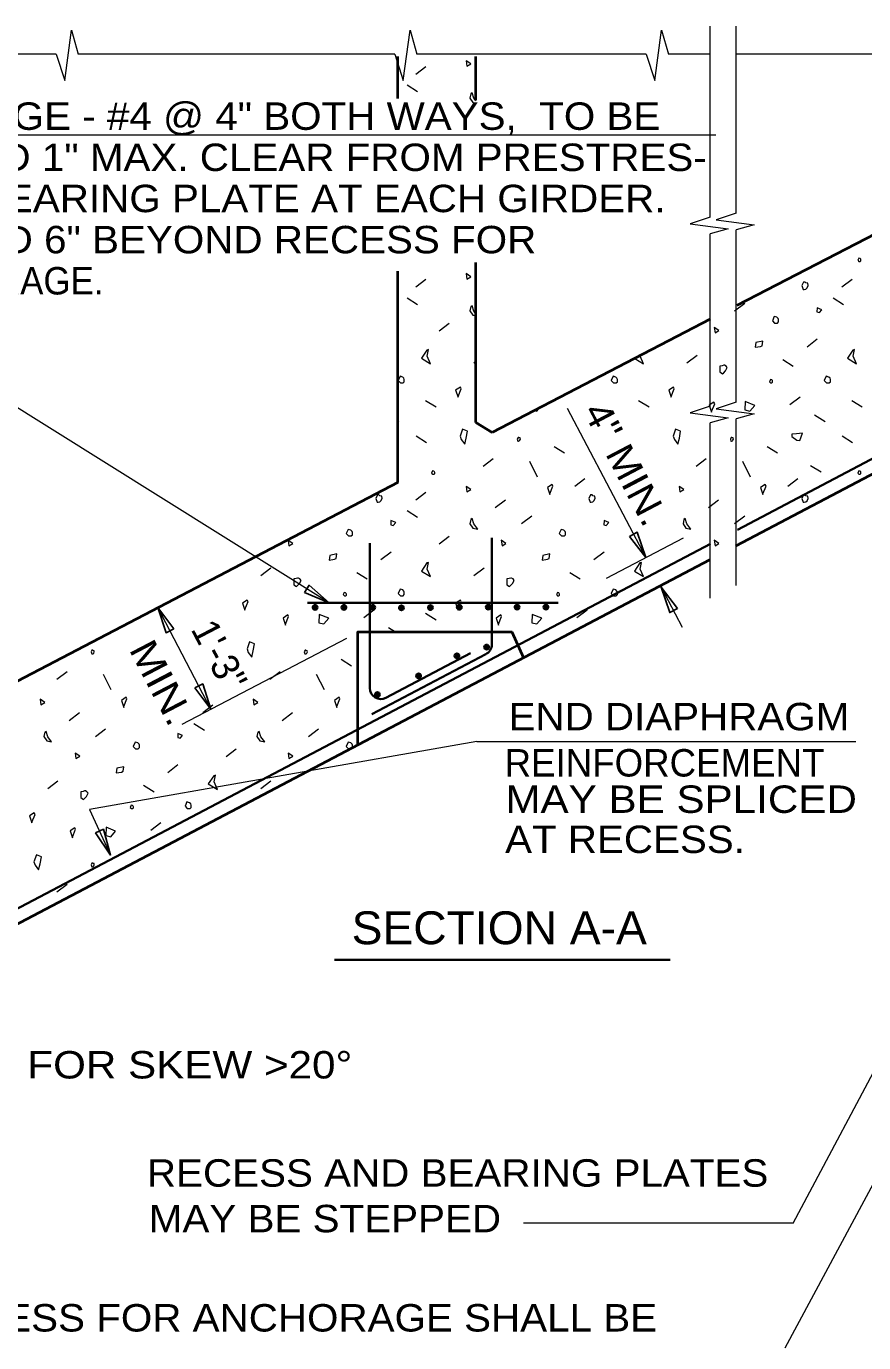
# Model space of a CAD drawing. Extents: x 0 to 22.7, y 0 to 15.6.
# Drawn here: x 3.45 to 6.629, y 5.449 to 10.447 of the extents above; entities that cross this region are included whole.
import ezdxf
from ezdxf.enums import TextEntityAlignment as Align

# ---------------------------------------------------------------- set-up
doc = ezdxf.new("R2010")
doc.units = 0
doc.header["$LTSCALE"] = 0.042
for name, color, linetype, lineweight in [('1', 7, 'Continuous', 13), ('3', 7, 'Continuous', 35), ('4', 7, 'Continuous', 13), ('7', 7, 'Continuous', 13)]:
    doc.layers.add(name, color=color, linetype=linetype, lineweight=lineweight)

msp = doc.modelspace()

# ---------------------------------------------------------------- linework, layer by layer
at = {"layer": '1'}
for p, q in [((6.04656, 10.19172), (6.04656, 10.44672)), ((6.14552, 10.19172), (6.14552, 10.44672)), ((3.56391, 10.3412), (2.69255, 10.3412)), ((4.2125, 10.3412), (3.6476, 10.3412)), ((4.84896, 10.3412), (4.2125, 10.3412)), ((5.80401, 10.3412), (4.93266, 10.3412)), ((6.04667, 10.3412), (5.88771, 10.3412)), ((6.04656, 9.72167), (6.04656, 10.33198)), ((6.60214, 10.3412), (6.14552, 10.3412)), ((6.14552, 9.73688), (6.14552, 10.33198)), ((7.23859, 10.3412), (6.60214, 10.3412)), ((6.04656, 9.00422), (6.04656, 9.6587)), ((6.14552, 9.01943), (6.14552, 9.67391)), ((6.14552, 8.32375), (6.14552, 8.9563)), ((6.04656, 8.27625), (6.04656, 8.94109))]:
    msp.add_line(p, q, dxfattribs=at)
at = {"layer": '1', "lineweight": 40}
for p, q in [((4.86115, 10.17276), (4.86115, 10.33198)), ((5.15703, 10.16615), (5.15703, 10.33198)), ((7.06307, 9.8613), (6.14734, 9.38661)), ((5.15703, 8.94219), (5.15703, 9.54979)), ((4.86115, 8.7151), (4.86115, 9.51661)), ((6.04703, 9.33464), (5.21896, 8.90536)), ((6.14396, 8.47438), (7.51385, 9.19516)), ((5.21896, 8.90536), (5.15703, 8.94219)), ((4.86115, 8.7151), (3.35927, 7.92995)), ((2.61615, 6.61818), (6.04656, 8.42313))]:
    msp.add_line(p, q, dxfattribs=at)
at = {"layer": '1'}
for points in [[(3.56391, 10.3412), (3.59641, 10.24068), (3.62188, 10.43167), (3.6476, 10.3412)], [(4.84896, 10.3412), (4.88151, 10.24057), (4.90698, 10.43167), (4.93266, 10.3412)], [(5.80401, 10.3412), (5.83651, 10.24068), (5.86198, 10.43167), (5.88771, 10.3412)], [(6.04656, 9.72167), (5.97078, 9.69714), (6.11443, 9.67802), (6.04656, 9.6587)], [(6.14552, 9.73688), (6.06974, 9.71234), (6.21339, 9.69323), (6.14552, 9.67391)], [(6.04656, 9.00422), (5.97078, 8.97948), (6.11443, 8.96052), (6.04656, 8.94109)], [(6.14552, 9.01943), (6.06974, 8.99469), (6.21339, 8.97573), (6.14552, 8.9563)]]:
    msp.add_lwpolyline(points, dxfattribs=at)
at = {"layer": '1', "lineweight": 40}
msp.add_lwpolyline([(4.70885, 7.71948), (4.70885, 8.14755), (5.29339, 8.14755), (5.33844, 8.04974)], dxfattribs=at)
at = {"layer": '3'}
for p, q in [((6.14974, 8.53552), (7.49031, 9.24089)), ((5.21776, 8.10036), (5.21776, 8.5049)), ((2.59677, 6.66609), (6.04719, 8.48156)), ((4.75453, 8.48479), (4.75453, 7.93464)), ((4.51828, 8.25786), (5.46922, 8.25786)), ((4.7624, 7.83563), (5.19547, 8.06349)), ((4.81563, 7.89776), (5.13677, 8.06672))]:
    msp.add_line(p, q, dxfattribs=at)
for centre, radius in [((4.54691, 8.24077), 0.0089), ((4.54691, 8.24077), 0.00593), ((4.65629, 8.24077), 0.0089), ((4.65629, 8.24077), 0.00593), ((4.76566, 8.24077), 0.0089), ((4.76566, 8.24077), 0.00593), ((4.87426, 8.2391), 0.0089), ((4.98426, 8.24009), 0.0089), ((4.98426, 8.24009), 0.00593), ((5.09426, 8.24108), 0.0089), ((5.09426, 8.24108), 0.00593), ((5.20426, 8.24212), 0.0089), ((5.20426, 8.24212), 0.00593), ((5.31363, 8.24212), 0.0089), ((5.31363, 8.24212), 0.00593), ((5.42301, 8.24212), 0.0089), ((5.42301, 8.24212), 0.00593), ((4.54691, 8.24077), 0.00297), ((4.65629, 8.24077), 0.00297), ((4.76566, 8.24077), 0.00297), ((4.87426, 8.2391), 0.00593), ((4.87426, 8.2391), 0.00297), ((4.98426, 8.24009), 0.00297), ((5.09426, 8.24108), 0.00297), ((5.20426, 8.24212), 0.00297), ((5.31363, 8.24212), 0.00297), ((5.42301, 8.24212), 0.00297), ((5.1977, 8.0903), 0.0089), ((5.1977, 8.0903), 0.00593), ((5.08535, 8.05686), 0.0089), ((5.08535, 8.05686), 0.00593), ((5.08535, 8.05686), 0.00297), ((5.1977, 8.0903), 0.00297), ((4.93962, 7.98072), 0.0089), ((4.93962, 7.98072), 0.00593), ((4.93962, 7.98072), 0.00297), ((4.78316, 7.90978), 0.0089), ((4.78316, 7.90978), 0.00593), ((4.78316, 7.90978), 0.00297)]:
    msp.add_circle(centre, radius, dxfattribs=at)
for centre, start, end in [((5.17609, 8.10037), 297.75042, 0), ((4.7962, 7.93463), 180, 297.75192)]:
    msp.add_arc(centre, 0.04167, start, end, dxfattribs=at)
at = {"layer": '4'}
for p, q in [((4.59969, 8.25786), (2.78911, 9.39073)), ((5.50302, 8.9974), (5.80167, 8.42979)), ((5.94391, 8.5038), (5.65109, 8.35068)), ((5.86094, 8.31708), (5.94031, 8.1663)), ((4.15151, 7.85401), (3.94932, 8.24078)), ((4.66563, 8.12281), (4.04078, 7.79615)), ((5.16109, 7.7313), (6.59948, 7.7313)), ((6.36161, 5.9025), (7.21276, 7.50573)), ((6.33057, 5.43), (7.13583, 6.92714)), ((6.36161, 5.9025), (5.33776, 5.9025))]:
    msp.add_line(p, q, dxfattribs=at)
at = {"layer": '4', "lineweight": 35}
msp.add_line((4.62057, 6.90219), (5.89427, 6.90219), dxfattribs=at)
at = {"layer": '4'}
for points in [[(6.0675, 10.03359), (2.78911, 10.03359), (2.78911, 9.39073)], [(5.16109, 7.7313), (3.69052, 7.47297), (3.7699, 7.30057)]]:
    msp.add_lwpolyline(points, dxfattribs=at)
at = {"layer": '4', "lineweight": 25}
for points in [[(5.74036, 8.51052), (5.76984, 8.52604), (5.80167, 8.42979)], [(4.50609, 8.29677), (4.52375, 8.32505), (4.59969, 8.25786)], [(5.92224, 8.23635), (5.89276, 8.22083), (5.86094, 8.31708)], [(4.01042, 8.1599), (3.98089, 8.14443), (3.94932, 8.24078)], [(4.09042, 7.9349), (4.11995, 7.95036), (4.15151, 7.85401)], [(3.71292, 7.38443), (3.74323, 7.39839), (3.7699, 7.30057)]]:
    msp.add_lwpolyline(points, close=True, dxfattribs=at)
at = {"layer": '7'}
for p, q in [((4.96771, 10.29339), (4.92917, 10.26406)), ((4.89573, 10.22411), (4.93531, 10.19911)), ((4.96771, 9.48542), (4.92917, 9.45615)), ((6.58526, 9.48542), (6.54677, 9.45615)), ((4.89573, 9.41615), (4.93531, 9.39115)), ((6.51333, 9.41615), (6.55292, 9.39115)), ((6.1776, 9.39464), (6.13911, 9.36531)), ((5.05594, 9.31818), (5.01745, 9.28885)), ((6.4526, 9.25844), (6.41411, 9.22911)), ((5.99677, 9.19724), (5.95828, 9.16792)), ((5.15703, 9.17365), (5.14948, 9.16792)), ((6.32219, 9.18151), (6.36182, 9.15656)), ((4.9662, 9.02667), (5.00573, 9.00182)), ((5.775, 9.02667), (5.81453, 9.00182)), ((6.38776, 9.03859), (6.34927, 9.00932)), ((6.58375, 9.02667), (6.62333, 9.00182)), ((4.86115, 8.94937), (4.8649, 8.94703)), ((6.44286, 8.97203), (6.4825, 8.94703)), ((4.93026, 8.89146), (4.96979, 8.86641)), ((5.45396, 8.85219), (5.49354, 8.82719)), ((6.26276, 8.85219), (6.30234, 8.82719)), ((6.54781, 8.89146), (6.5874, 8.86641)), ((5.22271, 8.80448), (5.18422, 8.77516)), ((5.36, 8.79557), (5.38932, 8.73677)), ((6.03151, 8.80448), (5.99302, 8.77516)), ((6.1688, 8.79557), (6.19813, 8.73677)), ((6.42786, 8.77995), (6.46745, 8.75495)), ((5.57073, 8.72943), (5.53219, 8.70016)), ((6.37948, 8.72943), (6.34099, 8.70016)), ((4.96771, 8.67745), (4.92917, 8.64818)), ((5.26938, 8.64792), (5.23089, 8.61865)), ((6.07818, 8.64792), (6.03969, 8.61865)), ((4.89573, 8.60823), (4.93531, 8.58323)), ((5.36885, 8.58667), (5.33031, 8.5574)), ((6.1776, 8.58667), (6.13911, 8.5574)), ((5.05594, 8.51021), (5.01745, 8.48094)), ((4.835, 8.45047), (4.79651, 8.42115)), ((5.6438, 8.45047), (5.60531, 8.42115)), ((4.37917, 8.38927), (4.34068, 8.36)), ((4.70458, 8.37354), (4.74422, 8.34859)), ((5.18797, 8.38927), (5.14948, 8.36)), ((5.51339, 8.37354), (5.55302, 8.34859)), ((4.77016, 8.23062), (4.73167, 8.20135)), ((4.9662, 8.2187), (5.00573, 8.19385)), ((5.57896, 8.23062), (5.54047, 8.20135)), ((4.82531, 8.16406), (4.85146, 8.14755)), ((3.60516, 7.99651), (3.56667, 7.96719)), ((4.41396, 7.99651), (4.37542, 7.96719)), ((4.64521, 8.04422), (4.68479, 8.01922)), ((3.7424, 7.9876), (3.77177, 7.9288)), ((4.5512, 7.9876), (4.58052, 7.9288)), ((4.15891, 7.86948), (4.12042, 7.84021)), ((3.65182, 7.83995), (3.61333, 7.81068)), ((4.08698, 7.80026), (4.12656, 7.77526)), ((4.46063, 7.83995), (4.42208, 7.81068)), ((3.75125, 7.7787), (3.71276, 7.74943)), ((4.56005, 7.7787), (4.52156, 7.74943)), ((4.24719, 7.70224), (4.20865, 7.67297)), ((4.02625, 7.6425), (3.98771, 7.61323)), ((3.57042, 7.5813), (3.53188, 7.55203)), ((3.89583, 7.56563), (3.93542, 7.54063)), ((4.37917, 7.5813), (4.34068, 7.55203)), ((3.96135, 7.42271), (3.92286, 7.39339)), ((3.60516, 7.18854), (3.56667, 7.15927))]:
    msp.add_line(p, q, dxfattribs=at)
for points in [[(5.12, 10.31599), (5.12292, 10.29531), (5.13771, 10.30422)], [(6.61042, 9.56703), (6.60672, 9.55891), (6.61104, 9.55443), (6.61635, 9.55443), (6.61854, 9.55677), (6.61854, 9.56109), (6.61781, 9.56323), (6.61552, 9.56563)], [(5.12, 9.50802), (5.12292, 9.48734), (5.13771, 9.49625)], [(6.3949, 9.46234), (6.39958, 9.4476), (6.4038, 9.4476), (6.40979, 9.44906), (6.41417, 9.45333), (6.41844, 9.46234), (6.41724, 9.47109), (6.40979, 9.4726), (6.40667, 9.47568), (6.40083, 9.47568)], [(6.45229, 9.37828), (6.45156, 9.36245), (6.46109, 9.36021), (6.47031, 9.37094)], [(6.06208, 9.30344), (6.06505, 9.28281), (6.07984, 9.29167)], [(6.2899, 9.345), (6.2825, 9.3288), (6.29115, 9.31979), (6.30177, 9.31979), (6.30609, 9.32453), (6.30609, 9.33313), (6.30464, 9.3374), (6.30005, 9.34214)], [(6.22031, 9.24615), (6.21734, 9.22849), (6.23802, 9.23146), (6.24385, 9.23432), (6.24682, 9.25203)], [(4.97063, 9.2176), (4.95005, 9.18672), (4.98469, 9.16599), (4.97208, 9.19401), (4.9774, 9.21969)], [(6.58823, 9.2176), (6.56766, 9.18672), (6.60229, 9.16599), (6.58964, 9.19401), (6.595, 9.21969)], [(6.08333, 9.15698), (6.08333, 9.13469), (6.09344, 9.1275), (6.09656, 9.13036), (6.10521, 9.13927), (6.11115, 9.15109), (6.10682, 9.15698), (6.10094, 9.15984), (6.09802, 9.15984), (6.09224, 9.15823)], [(4.86917, 9.11802), (4.86177, 9.10182), (4.87042, 9.09281), (4.88099, 9.09281), (4.88531, 9.09755), (4.88531, 9.10615), (4.88385, 9.11042), (4.87927, 9.11516)], [(5.67797, 9.11802), (5.67052, 9.10182), (5.67922, 9.09281), (5.68979, 9.09281), (5.69411, 9.09755), (5.69411, 9.10615), (5.69266, 9.11042), (5.68807, 9.11516)], [(6.27516, 9.10552), (6.27146, 9.0974), (6.27578, 9.09292), (6.28109, 9.09292), (6.28323, 9.09526), (6.28323, 9.09958), (6.2825, 9.10172), (6.28021, 9.10406)], [(6.48677, 9.11802), (6.47932, 9.10182), (6.48802, 9.09281), (6.49859, 9.09281), (6.50292, 9.09755), (6.50292, 9.10615), (6.50146, 9.11042), (6.49688, 9.11516)], [(5.08021, 9.06484), (5.08927, 9.03828), (5.08927, 9.04115), (5.10109, 9.07073), (5.09813, 9.07661)], [(5.88896, 9.06484), (5.89807, 9.03828), (5.89807, 9.04115), (5.9099, 9.07073), (5.90688, 9.07661)], [(6.04271, 9.00828), (6.05188, 8.98172), (6.05188, 8.98458), (6.06365, 9.01417), (6.06063, 9.02005)], [(6.17979, 9.02234), (6.17839, 8.99068), (6.1975, 8.98625), (6.21594, 9.0076)], [(5.10604, 8.9174), (5.09714, 8.89083), (5.10167, 8.8776), (5.1149, 8.8599), (5.12078, 8.88349), (5.12521, 8.91005)], [(5.91484, 8.9174), (5.90594, 8.89083), (5.91047, 8.8776), (5.9237, 8.8599), (5.92958, 8.88349), (5.93401, 8.91005)], [(6.37458, 8.89979), (6.35693, 8.89833), (6.35693, 8.88948), (6.37609, 8.87625), (6.38646, 8.87479), (6.39677, 8.90276)], [(5.31438, 8.87958), (5.31672, 8.87219), (5.31885, 8.87219), (5.32188, 8.87292), (5.32401, 8.8751), (5.32615, 8.87958), (5.32557, 8.88396), (5.32188, 8.88474), (5.32031, 8.88625), (5.31734, 8.88625)], [(6.12318, 8.87958), (6.12552, 8.87219), (6.12766, 8.87219), (6.13063, 8.87292), (6.13281, 8.8751), (6.13495, 8.87958), (6.13438, 8.88396), (6.13063, 8.88474), (6.12906, 8.88625), (6.12615, 8.88625)], [(4.99286, 8.75906), (4.98917, 8.75094), (4.99349, 8.74646), (4.9988, 8.74646), (5.00094, 8.7488), (5.00094, 8.75313), (5.00021, 8.75526), (4.99797, 8.75766)], [(6.61042, 8.75906), (6.60672, 8.75094), (6.61104, 8.74646), (6.61635, 8.74646), (6.61854, 8.7488), (6.61854, 8.75313), (6.61781, 8.75526), (6.61552, 8.75766)], [(5.12, 8.70005), (5.12292, 8.67938), (5.13771, 8.68828)], [(5.4288, 8.69573), (5.43792, 8.66917), (5.43792, 8.67203), (5.44969, 8.70161), (5.44672, 8.7075)], [(5.92875, 8.70005), (5.93172, 8.67938), (5.94651, 8.68828)], [(6.2376, 8.69573), (6.24672, 8.66917), (6.24672, 8.67203), (6.25849, 8.70161), (6.25552, 8.7075)], [(4.77729, 8.65437), (4.78198, 8.63964), (4.78625, 8.63964), (4.79224, 8.64109), (4.79656, 8.64536), (4.80083, 8.65437), (4.79964, 8.66313), (4.79224, 8.66469), (4.78911, 8.66771), (4.78323, 8.66771)], [(5.58609, 8.65437), (5.59078, 8.63964), (5.595, 8.63964), (5.60104, 8.64109), (5.60536, 8.64536), (5.60964, 8.65437), (5.60844, 8.66313), (5.60104, 8.66469), (5.59792, 8.66771), (5.59203, 8.66771)], [(6.3949, 8.65437), (6.39958, 8.63964), (6.4038, 8.63964), (6.40979, 8.64109), (6.41417, 8.64536), (6.41844, 8.65437), (6.41724, 8.66313), (6.40979, 8.66469), (6.40667, 8.66771), (6.40083, 8.66771)], [(4.83469, 8.57031), (4.83396, 8.55448), (4.84354, 8.55229), (4.85276, 8.56297)], [(5.13792, 8.57469), (5.13469, 8.55813), (5.14568, 8.54188), (5.16411, 8.53823), (5.14943, 8.55776), (5.14313, 8.57802)], [(5.64349, 8.57031), (5.64276, 8.55448), (5.65229, 8.55229), (5.66156, 8.56297)], [(5.94672, 8.57469), (5.94349, 8.55813), (5.95448, 8.54188), (5.97292, 8.53823), (5.95823, 8.55776), (5.95188, 8.57802)], [(4.67234, 8.53703), (4.6649, 8.52083), (4.67359, 8.51187), (4.68417, 8.51187), (4.68849, 8.51656), (4.68849, 8.52521), (4.68703, 8.52943), (4.68245, 8.53417)], [(5.48115, 8.53703), (5.4737, 8.52083), (5.4824, 8.51187), (5.49297, 8.51187), (5.49729, 8.51656), (5.49729, 8.52521), (5.49583, 8.52943), (5.49125, 8.53417)], [(5.25328, 8.49547), (5.25625, 8.47484), (5.27104, 8.4837)], [(6.06208, 8.49547), (6.06505, 8.47484), (6.07984, 8.4837)], [(4.60276, 8.43818), (4.59979, 8.42052), (4.62042, 8.42349), (4.6263, 8.42635), (4.62927, 8.44406)], [(4.97063, 8.40964), (4.95005, 8.37875), (4.98469, 8.35802), (4.97208, 8.38604), (4.9774, 8.41177)], [(5.41156, 8.43818), (5.40854, 8.42052), (5.42922, 8.42349), (5.4351, 8.42635), (5.43802, 8.44406)], [(5.77943, 8.40964), (5.75885, 8.37875), (5.79349, 8.35802), (5.78083, 8.38604), (5.7862, 8.41177)], [(4.46573, 8.34906), (4.46573, 8.32672), (4.47589, 8.31953), (4.47896, 8.3224), (4.4876, 8.3313), (4.49354, 8.34313), (4.48927, 8.34906), (4.48333, 8.35187), (4.48047, 8.35187), (4.47469, 8.35026)], [(5.27453, 8.34906), (5.27453, 8.32672), (5.28469, 8.31953), (5.28776, 8.3224), (5.29641, 8.3313), (5.30234, 8.34313), (5.29802, 8.34906), (5.29214, 8.35187), (5.28927, 8.35187), (5.28344, 8.35026)], [(4.6576, 8.29755), (4.65385, 8.28943), (4.65823, 8.28495), (4.66349, 8.28495), (4.66568, 8.28729), (4.66568, 8.29161), (4.66495, 8.29375), (4.66266, 8.29609)], [(4.86917, 8.31005), (4.86177, 8.29385), (4.87042, 8.2849), (4.88099, 8.2849), (4.88531, 8.28958), (4.88531, 8.29823), (4.88385, 8.30245), (4.87927, 8.30719)], [(5.46635, 8.29755), (5.46266, 8.28943), (5.46698, 8.28495), (5.47229, 8.28495), (5.47448, 8.28729), (5.47448, 8.29161), (5.47375, 8.29375), (5.47146, 8.29609)], [(5.67797, 8.31005), (5.67052, 8.29385), (5.67922, 8.2849), (5.68979, 8.2849), (5.69411, 8.28958), (5.69411, 8.29823), (5.69266, 8.30245), (5.68807, 8.30719)], [(4.27141, 8.25688), (4.28052, 8.23031), (4.28052, 8.23318), (4.29229, 8.26276), (4.28932, 8.26865)], [(5.08021, 8.25688), (5.08927, 8.23031), (5.08927, 8.23318), (5.10109, 8.26276), (5.09813, 8.26865)], [(4.42516, 8.20031), (4.43427, 8.17375), (4.43427, 8.17661), (4.44604, 8.20625), (4.44302, 8.21208)], [(4.56219, 8.21438), (4.56078, 8.18271), (4.5799, 8.17828), (4.59833, 8.19964)], [(5.23396, 8.20031), (5.24307, 8.17375), (5.24307, 8.17661), (5.25484, 8.20625), (5.25182, 8.21208)], [(5.37099, 8.21438), (5.36958, 8.18271), (5.3887, 8.17828), (5.40714, 8.19964)], [(4.29729, 8.10943), (4.28833, 8.08292), (4.29286, 8.06964), (4.30609, 8.05193), (4.31198, 8.07552), (4.31641, 8.10208)], [(3.69682, 8.07161), (3.69917, 8.06422), (3.70125, 8.06422), (3.70427, 8.065), (3.70646, 8.06714), (3.70859, 8.07161), (3.70797, 8.07604), (3.70427, 8.07677), (3.70271, 8.07833), (3.69979, 8.07833)], [(4.50563, 8.07161), (4.50792, 8.06422), (4.51005, 8.06422), (4.51307, 8.065), (4.51521, 8.06714), (4.5174, 8.07161), (4.51677, 8.07604), (4.51307, 8.07677), (4.51151, 8.07833), (4.50854, 8.07833)], [(3.81125, 7.88781), (3.82036, 7.8612), (3.82036, 7.86406), (3.83214, 7.89365), (3.82911, 7.89953)], [(4.62, 7.88781), (4.62917, 7.8612), (4.62917, 7.86406), (4.64094, 7.89365), (4.63792, 7.89953)], [(3.5024, 7.89208), (3.50536, 7.87146), (3.52016, 7.88031)], [(4.3112, 7.89208), (4.31417, 7.87146), (4.32896, 7.88031)], [(3.52036, 7.76677), (3.51708, 7.75016), (3.52813, 7.73391), (3.54656, 7.73026), (3.53182, 7.74979), (3.52552, 7.77005)], [(4.02589, 7.76234), (4.02521, 7.74656), (4.03474, 7.74432), (4.04396, 7.755)], [(4.32917, 7.76677), (4.32589, 7.75016), (4.33688, 7.73391), (4.35531, 7.73026), (4.34063, 7.74979), (4.33432, 7.77005)], [(3.86354, 7.72906), (3.85615, 7.71292), (3.86479, 7.70391), (3.87536, 7.70391), (3.87969, 7.70859), (3.87969, 7.71724), (3.87823, 7.72146), (3.87365, 7.72625)], [(3.63568, 7.6875), (3.63865, 7.66688), (3.65344, 7.67573)], [(4.44448, 7.6875), (4.44745, 7.66688), (4.46224, 7.67573)], [(3.79396, 7.63021), (3.79099, 7.61255), (3.81167, 7.61552), (3.8175, 7.61844), (3.82047, 7.63609)], [(4.16188, 7.60167), (4.14125, 7.57083), (4.17594, 7.55005), (4.16328, 7.57813), (4.16859, 7.6038)], [(3.65698, 7.54109), (3.65698, 7.51875), (3.66708, 7.51156), (3.67016, 7.51448), (3.67885, 7.52333), (3.68474, 7.53516), (3.68047, 7.54109), (3.67453, 7.54391), (3.67167, 7.54391), (3.66589, 7.54229)], [(4.06036, 7.50208), (4.05297, 7.48594), (4.06161, 7.47693), (4.07219, 7.47693), (4.07656, 7.48161), (4.07656, 7.49026), (4.0751, 7.49448), (4.07052, 7.49927)], [(3.4626, 7.44896), (3.47172, 7.42234), (3.47172, 7.42521), (3.48354, 7.45479), (3.48052, 7.46068)], [(3.8488, 7.48958), (3.8451, 7.48146), (3.84943, 7.47698), (3.85469, 7.47698), (3.85688, 7.47932), (3.85688, 7.48365), (3.85615, 7.48578), (3.85385, 7.48813)], [(3.61635, 7.3924), (3.62547, 7.36583), (3.62547, 7.36865), (3.63724, 7.39828), (3.63427, 7.40417)], [(3.75344, 7.40646), (3.75198, 7.37479), (3.77115, 7.37031), (3.78953, 7.39167)], [(3.48849, 7.30146), (3.47953, 7.27495), (3.48406, 7.26167), (3.49729, 7.24396), (3.50318, 7.26755), (3.5076, 7.29411)], [(3.69682, 7.26365), (3.69917, 7.25625), (3.70125, 7.25625), (3.70427, 7.25703), (3.70646, 7.25917), (3.70859, 7.26365), (3.70797, 7.26807), (3.70427, 7.2688), (3.70271, 7.27036), (3.69979, 7.27036)]]:
    msp.add_lwpolyline(points, close=True, dxfattribs=at)
for points in [[(5.13792, 10.19063), (5.13469, 10.17401), (5.14568, 10.15781), (5.15703, 10.15557)], [(5.15703, 10.16354), (5.14943, 10.17365), (5.14313, 10.19391), (5.13792, 10.19063)], [(5.13792, 9.38266), (5.13469, 9.36604), (5.14568, 9.34984), (5.15703, 9.3476)], [(5.15703, 9.35562), (5.14943, 9.36573), (5.14313, 9.38594), (5.13792, 9.38266)], [(5.76021, 9.18594), (5.79349, 9.16599), (5.78083, 9.19401), (5.78146, 9.19693)], [(5.37922, 8.98844), (5.3887, 8.98625), (5.39979, 8.99911)], [(4.44458, 8.4949), (4.44745, 8.47484), (4.46224, 8.4837), (4.445, 8.4951)], [(4.67234, 7.72906), (4.6649, 7.71292), (4.67359, 7.70391), (4.67917, 7.70391)], [(4.68849, 7.7088), (4.68849, 7.71724), (4.68703, 7.72146), (4.68245, 7.72625), (4.67234, 7.72906)]]:
    msp.add_lwpolyline(points, dxfattribs=at)

# ---------------------------------------------------------------- texts
at = {"layer": '4'}
for s, height, width, p in [('GRILLAGE - #4 @ 4" BOTH WAYS,  TO BE', 0.1042, 1.1, (2.85354, 10.0537)), ('PLACED 1" MAX. CLEAR FROM PRESTRES-', 0.1042, 1.1, (2.85354, 9.89745)), ('SING BEARING PLATE AT EACH GIRDER.', 0.1042, 1.1, (2.85354, 9.7412)), ('EXTEND 6" BEYOND RECESS FOR', 0.1042, 1.1, (2.85354, 9.58495)), ('ANCHORAGE.', 0.1042, 0.95, (2.85354, 9.4287)), ('END DIAPHRAGM ', 0.1041, 1.1, (5.28115, 7.77422)), ('MAY BE SPLICED ', 0.1041, 1.15, (5.26906, 7.46063)), ('AT RECESS.', 0.1041, 1.1, (5.26797, 7.30833)), ('*OMIT FOR SKEW >20°', 0.1041, 1.15, (2.9474, 6.45234)), ('RECESS AND BEARING PLATES', 0.1042, 1.1, (3.90807, 6.04156)), ('MAY BE STEPPED', 0.1042, 1.1, (3.91552, 5.86839)), ('RECESS FOR ANCHORAGE SHALL BE', 0.1042, 1.1, (3.04286, 5.49167))]:
    msp.add_text(s, height=height, dxfattribs=dict(at, width=width)).set_placement(p)
at = {"layer": '4', "width": 1.1}
msp.add_text('4" MIN.', height=0.1041, rotation=297.751, dxfattribs=at).set_placement((5.79719, 8.53869), align=Align.RIGHT)
at = {"layer": '4'}
msp.add_text('1\'-3"', height=0.1042, rotation=297.599, dxfattribs=at).set_placement((4.13734, 8.03569), align=Align.CENTER)
at = {"layer": '4', "width": 1.15}
msp.add_text('MIN.', height=0.1042, rotation=297.599, dxfattribs=at).set_placement((3.9169, 7.93132), align=Align.CENTER)
at = {"layer": '4'}
msp.add_text('REINFORCEMENT', height=0.1041, dxfattribs=at).set_placement((5.26604, 7.5987))
at = {"layer": '4', "width": 1.05}
msp.add_text('SECTION A-A', height=0.1249, dxfattribs=at).set_placement((5.24573, 6.96203), align=Align.CENTER)

doc.saveas('drawing.dxf')
